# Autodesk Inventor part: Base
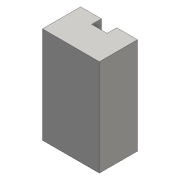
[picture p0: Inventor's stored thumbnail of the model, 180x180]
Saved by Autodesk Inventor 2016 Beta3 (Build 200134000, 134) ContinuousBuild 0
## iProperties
Created: 2016-03
Part Number: Base
Material: Generic
Document SubType Name: Modeling
Designer: Gaurav
Density: 1 g/cm^3
Appearance: Default
Author: Gaurav
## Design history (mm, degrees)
sketch "Sketch1"
  geometry: L1 (14.722, 9.87)-(14.722, -9.87); L2 (14.722, -9.87)-(-14.722, -9.87); L3 (-14.722, -9.87)-(-14.722, 9.87); L4 (-14.722, 9.87)-(14.722, -9.87); L5 (14.722, 9.87)-(-14.722, -9.87); L6 (-4, 4.87)-(-4, 9.87); L7 (4, 9.87)-(4, 4.87); L8 (4, 4.87)-(-4, 4.87); L9 (-4, 4.87)-(4, 9.87); L10 (-4, 9.87)-(4, 4.87); L11 (-14.722, 9.87)-(-4, 9.87); L12 (4, 9.87)-(14.722, 9.87); 4 further points
  constraints: 24 end point, 6 midpoint, 4 parallel, 2 horizontal, 2 perpendicular, 1 vertical alignment
  dimensions: "d2" = 5 distance of L7.start L7.end; "d3" = 8 distance of L7.end L6.start
extrude "Extrusion1" new body sketch "Sketch1" distance "d4" = 50; taper "d5" = 0 deg
body "Solid1"
